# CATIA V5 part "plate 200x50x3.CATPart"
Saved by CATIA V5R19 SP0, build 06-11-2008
Part number: plate 200x50x3
Bounding box of the stored display mesh (mm): x -200 to 0, y 0 to 3, z 0 to 50
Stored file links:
  D:\AUTO BATCH (BHEL)\Collecting Hopper 2\plate 200x50x3.CATPart
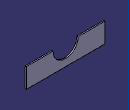
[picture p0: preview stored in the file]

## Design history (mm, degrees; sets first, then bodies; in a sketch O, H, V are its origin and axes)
SheetMetalParameters1: BendRadius 3, ReliefAxialLength 2, ReliefRadialLength 1, MinimumBendRadius 0, Thickness 3, KFactor 0.325257 {= log(min(100,max(20*SheetMetalParameters1.BendRadius,SheetMetalParameters1.Thickness)/SheetMetalParameters1.Thickness))/log(100)/2}
Body1 (main body)
  Sketch1 on zx-plane, origin (0, 0, 0), H (-1, 0, 0), V (0, 0, 1)
    line L1 (0, 0) -> (200, 0)
    line L2 (200, 0) -> (200, 50)
    line L3 (200, 50) -> (0, 50)
    line L4 (0, 50) -> (0, 0)
    length L1 = 200
    length L2 = 50
    horizontal: L1 H, L3 H
    vertical: L2 V, L4 V
  Wall1: Thickness 3, Profile Sketch1
  Sketch2 on face of Wall1, origin (0, 3, 0), H (-1, 0, 0), V (0, 0, 1)
    circle A1 centre (100, 50) radius 32
    point P1 (100, 50)
    reference projected line E1 (306, 50) -> (0, 50) from edge [face of Wall1 | face of Wall1]
    reference projected line E2 (0, 50) -> (0, 0) from edge [face of Wall1 | face of Wall1]
    radius A1 = 32
    distance P1 E2 = 100
    coincidence: P1 E1
  CutOut1: StartLimit through (limit type 2), Orientation true, Profile Sketch2, Direction Sketch2, EndLimit through (limit type 2)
